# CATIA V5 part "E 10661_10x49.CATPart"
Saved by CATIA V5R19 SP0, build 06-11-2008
Part number: E 10661_10x49
Definition: E 10661_10x49
Nomenclature: E 10661_10x49
Source: Unknown
Description: PART--DESC
Bounding box of the stored display mesh (mm): x 20 to 30, y -4.99 to 4.99, z -45 to 4
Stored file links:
  C:\Users\jsmid\Desktop\DP_Smidak_Forma LEGO\E 10661_10x49.CATPart
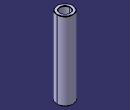
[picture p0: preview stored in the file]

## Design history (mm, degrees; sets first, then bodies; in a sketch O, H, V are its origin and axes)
Body1 "E 10661_10x49" (main body)
  Solid1: solid without history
